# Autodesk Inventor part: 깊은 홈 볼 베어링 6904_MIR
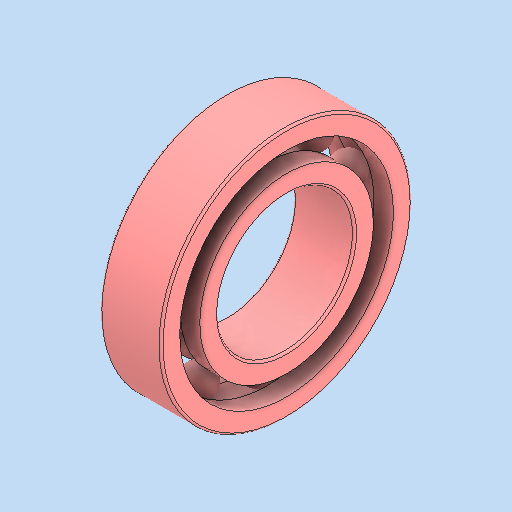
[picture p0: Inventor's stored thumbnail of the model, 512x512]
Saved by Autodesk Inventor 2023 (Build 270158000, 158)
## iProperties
Created: 2026-06
Part Number: 깊은 홈 볼 베어링 6904_MIR
Material: 강철, 연강
Description: 깊은 그루브 볼 베어링
Document SubType Name: Modeling
Designer: home
Density: 7.85 g/cm^3
Appearance: 기본값
Author: jhkim
Sending System: Autodesk Inventor 2027
Preprocessor: ST-DEVELOPER v20.1
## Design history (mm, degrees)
derived "깊은 홈 볼 베어링 6904.ipt"
feature "솔리드1::깊은 홈 볼 베어링 6904.ipt"
feature "솔리드2::깊은 홈 볼 베어링 6904.ipt"
feature "솔리드3::깊은 홈 볼 베어링 6904.ipt"
feature "솔리드4::깊은 홈 볼 베어링 6904.ipt"
feature "솔리드5::깊은 홈 볼 베어링 6904.ipt"
feature "솔리드6::깊은 홈 볼 베어링 6904.ipt"
feature "솔리드7::깊은 홈 볼 베어링 6904.ipt"
feature "솔리드8::깊은 홈 볼 베어링 6904.ipt"
feature "솔리드9::깊은 홈 볼 베어링 6904.ipt"
feature "솔리드10::깊은 홈 볼 베어링 6904.ipt"
feature "솔리드11::깊은 홈 볼 베어링 6904.ipt"
feature "솔리드12::깊은 홈 볼 베어링 6904.ipt"
tag "피쳐 태그1"
node "솔리드1"
node "솔리드2"
node "솔리드3"
node "솔리드4"
node "솔리드5"
node "솔리드6"
node "솔리드7"
node "솔리드8"
node "솔리드9"
node "솔리드10"
node "솔리드11"
node "솔리드12"
